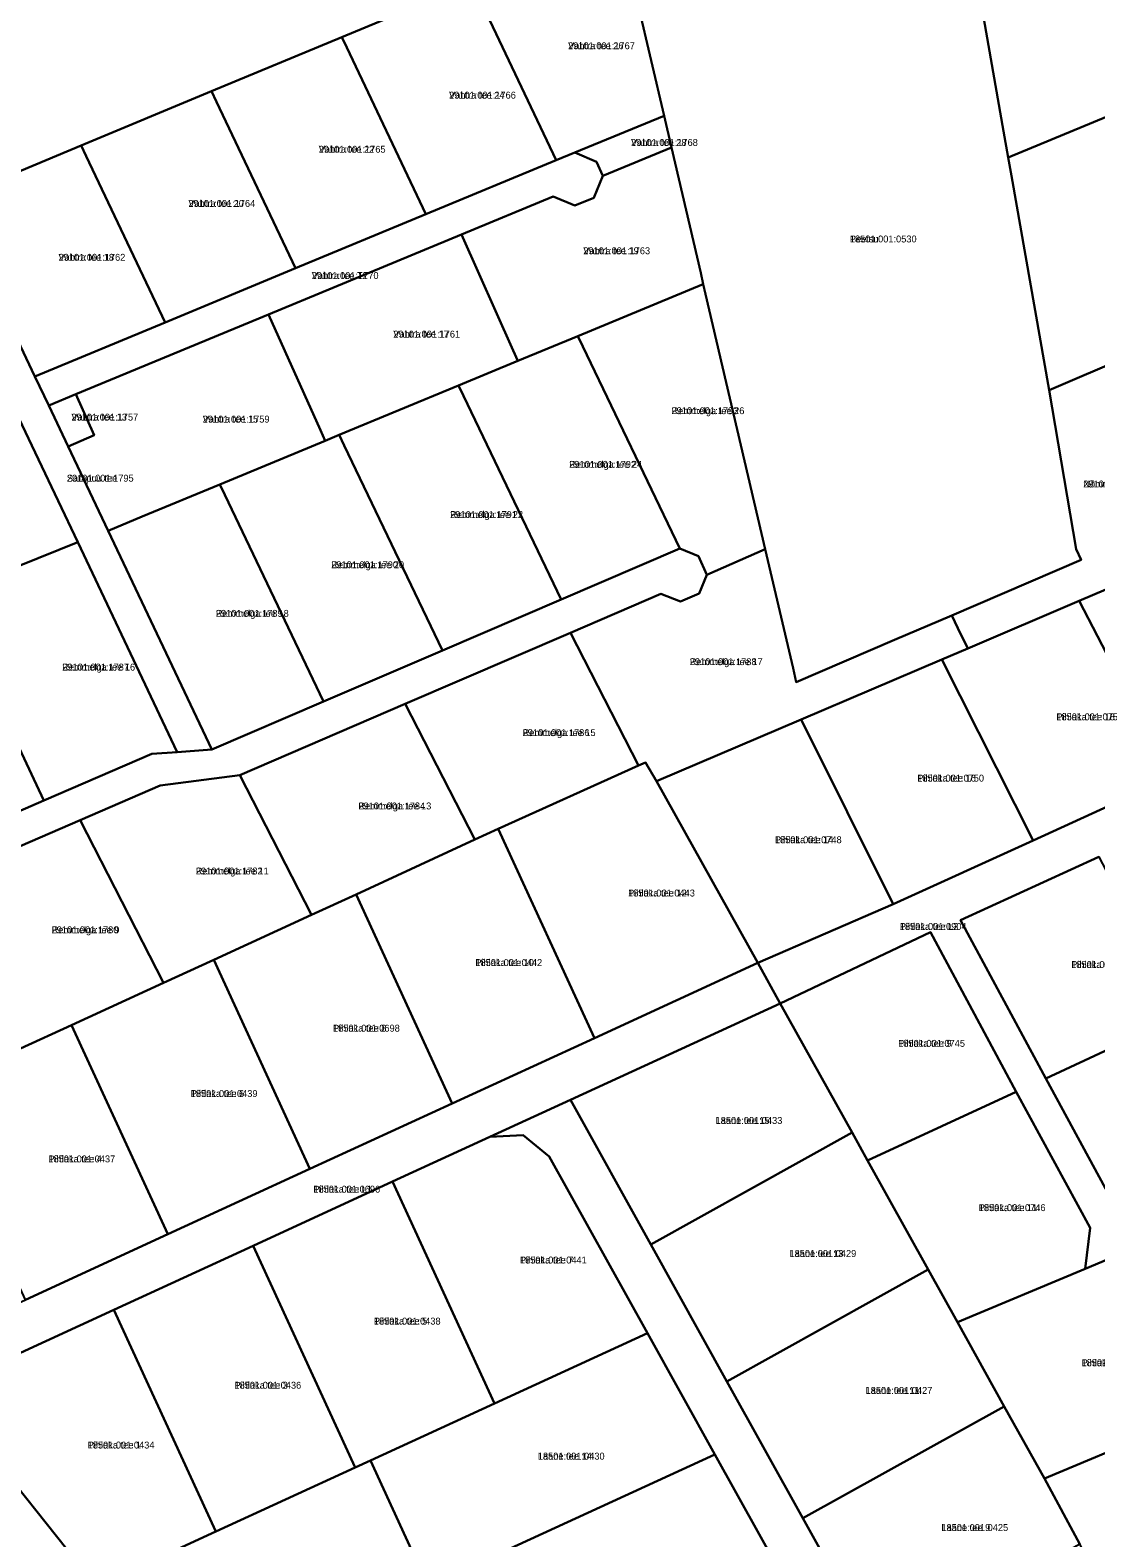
# Model space of a CAD drawing. Extents: x 660838 to 697091, y 6455678 to 6479886.
# Drawn here: x 663522.4 to 663753.8, y 6468685 to 6469012.3 of the extents above; entities that cross this region are included whole.
import ezdxf

# ---------------------------------------------------------------- set-up
doc = ezdxf.new("R2010")
doc.units = 0
for name, color, linetype in [('L_AADRESS', 7, 'Continuous'), ('PIIR', 7, 'Continuous'), ('TUNNUS', 7, 'Continuous')]:
    doc.layers.add(name, color=color, linetype=linetype)

msp = doc.modelspace()

# ---------------------------------------------------------------- linework, layer by layer
at = {"layer": 'PIIR'}
for points in [[(663713.62, 6469105.91), (663746.93, 6469119.34), (663749.47, 6469109.68), (663756.71, 6469091.04), (663760.88, 6469081.29), (663769.48, 6469063.27), (663778.44, 6469046.32), (663796.85, 6469010.36), (663794.27, 6469009.28), (663762.57, 6468996.15), (663734.77, 6468984.63), (663733.79, 6468990.38), (663721.13, 6469062.36), (663720.66, 6469065.11), (663720.33, 6469067.06)], [(663486.87, 6469014.31), (663713.62, 6469105.91), (663720.33, 6469067.06), (663720.66, 6469065.11), (663650.19, 6469035.8), (663618.39, 6469022.56), (663590.11, 6469010.8), (663561.82, 6468999.03), (663533.52, 6468987.26), (663507.5, 6468976.43), (663507.24, 6468975.83), (663505.45, 6468975.08)], [(663720.66, 6469065.11), (663721.13, 6469062.36), (663733.79, 6468990.38), (663734.77, 6468984.63), (663735.47, 6468980.66), (663743.64, 6468934.13), (663749.54, 6468899.66), (663750.6, 6468897.35), (663722.52, 6468885.28), (663710.12, 6468879.95), (663688.77, 6468870.78), (663688.07, 6468873.8), (663682.01, 6468899.68), (663669.09, 6468955.03), (663668.58, 6468957.2), (663668.01, 6468959.61), (663661.64, 6468986.83), (663660.05, 6468993.7), (663651.59, 6469029.84), (663650.19, 6469035.8)], [(663618.39, 6469022.56), (663650.19, 6469035.8), (663651.59, 6469029.84), (663660.05, 6468993.7), (663640.72, 6468985.74), (663636.66, 6468984.06), (663619.46, 6469020.3)], [(663590.11, 6469010.8), (663618.39, 6469022.56), (663619.46, 6469020.3), (663636.66, 6468984.06), (663608.35, 6468972.33), (663591.18, 6469008.54)], [(663561.82, 6468999.03), (663590.11, 6469010.8), (663591.18, 6469008.54), (663608.35, 6468972.33), (663580.05, 6468960.61), (663562.89, 6468996.77)], [(663533.52, 6468987.26), (663561.82, 6468999.03), (663562.89, 6468996.77), (663580.05, 6468960.61), (663551.73, 6468948.87), (663534.59, 6468984.99)], [(663734.77, 6468984.63), (663762.57, 6468996.15), (663764.4, 6468992.6), (663785.23, 6468951.96), (663760.77, 6468941.45), (663743.64, 6468934.13), (663735.47, 6468980.66)], [(663640.72, 6468985.74), (663660.05, 6468993.7), (663661.64, 6468986.83), (663646.75, 6468980.66), (663645.42, 6468983.74)], [(663507.5, 6468976.43), (663533.52, 6468987.26), (663534.59, 6468984.99), (663551.73, 6468948.87), (663523.45, 6468937.16), (663505.45, 6468975.08), (663507.24, 6468975.83)], [(663636.66, 6468984.06), (663640.72, 6468985.74), (663645.42, 6468983.74), (663646.75, 6468980.66), (663644.79, 6468975.93), (663640.72, 6468974.24), (663635.99, 6468976.21), (663616.08, 6468967.96), (663574.21, 6468950.61), (663532.35, 6468933.27), (663526.45, 6468930.82), (663523.45, 6468937.16), (663551.73, 6468948.87), (663580.05, 6468960.61), (663608.35, 6468972.33)], [(663646.75, 6468980.66), (663661.64, 6468986.83), (663668.01, 6468959.61), (663668.58, 6468957.2), (663641.33, 6468945.9), (663628.34, 6468940.52), (663627.32, 6468942.8), (663616.08, 6468967.96), (663635.99, 6468976.21), (663640.72, 6468974.24), (663644.79, 6468975.93)], [(663498.96, 6468972.37), (663505.45, 6468975.08), (663523.45, 6468937.16), (663526.45, 6468930.82), (663530.66, 6468921.94), (663539.34, 6468903.64), (663561.84, 6468856.19), (663554.36, 6468855.61), (663532.75, 6468901.15), (663519.97, 6468928.09), (663516.97, 6468934.43)], [(663574.21, 6468950.61), (663616.08, 6468967.96), (663627.32, 6468942.8), (663628.34, 6468940.52), (663615.44, 6468935.17), (663589.51, 6468924.43), (663586.48, 6468923.17), (663585.46, 6468925.45)], [(663641.33, 6468945.9), (663668.58, 6468957.2), (663669.09, 6468955.03), (663682.01, 6468899.68), (663669.31, 6468894.09), (663667.57, 6468898.13), (663663.49, 6468899.77), (663642.41, 6468943.65)], [(663532.35, 6468933.27), (663574.21, 6468950.61), (663585.46, 6468925.45), (663586.48, 6468923.17), (663563.61, 6468913.7), (663546.73, 6468906.7), (663539.34, 6468903.64), (663530.66, 6468921.94), (663536.32, 6468924.39)], [(663628.34, 6468940.52), (663641.33, 6468945.9), (663642.41, 6468943.65), (663663.49, 6468899.77), (663637.7, 6468888.71), (663616.52, 6468932.92), (663615.44, 6468935.17)], [(663743.64, 6468934.13), (663760.77, 6468941.45), (663759.06, 6468937.44), (663760.77, 6468933.32), (663763.65, 6468932.16), (663779.64, 6468900.95), (663750.22, 6468888.4), (663725.98, 6468878.05), (663723.87, 6468882.46), (663722.52, 6468885.28), (663750.6, 6468897.35), (663749.54, 6468899.66)], [(663526.45, 6468930.82), (663532.35, 6468933.27), (663536.32, 6468924.39), (663530.66, 6468921.94)], [(663589.51, 6468924.43), (663615.44, 6468935.17), (663616.52, 6468932.92), (663637.7, 6468888.71), (663611.97, 6468877.68), (663590.6, 6468922.17)], [(663479.86, 6468911.75), (663519.97, 6468928.09), (663532.75, 6468901.15), (663520.04, 6468896.06), (663518.06, 6468895.26), (663504.39, 6468889.72), (663492.61, 6468884.94), (663491.54, 6468887.21)], [(663586.48, 6468923.17), (663589.51, 6468924.43), (663590.6, 6468922.17), (663611.97, 6468877.68), (663586.13, 6468866.6), (663564.69, 6468911.44), (663563.61, 6468913.7)], [(663546.73, 6468906.7), (663563.61, 6468913.7), (663564.69, 6468911.44), (663586.13, 6468866.6), (663561.84, 6468856.19), (663539.34, 6468903.64)], [(663520.04, 6468896.06), (663532.75, 6468901.15), (663554.36, 6468855.61), (663548.83, 6468855.19), (663525.39, 6468845.05), (663505.46, 6468887.45), (663504.39, 6468889.72), (663518.06, 6468895.26)], [(663669.31, 6468894.09), (663682.01, 6468899.68), (663688.07, 6468873.8), (663688.77, 6468870.78), (663710.12, 6468879.95), (663722.52, 6468885.28), (663723.87, 6468882.46), (663725.98, 6468878.05), (663720.37, 6468875.68), (663689.86, 6468862.67), (663658.45, 6468849.26), (663656.03, 6468853.33), (663654.54, 6468852.67), (663639.77, 6468881.51), (663659.37, 6468889.97), (663663.63, 6468888.27), (663667.67, 6468890)], [(663750.22, 6468888.4), (663779.64, 6468900.95), (663779.88, 6468901.05), (663799.48, 6468863.6), (663770.09, 6468850.07)], [(663492.61, 6468884.94), (663504.39, 6468889.72), (663505.46, 6468887.45), (663525.39, 6468845.05), (663498.76, 6468833.53), (663478.54, 6468876.54), (663477.48, 6468878.81)], [(663720.37, 6468875.68), (663725.98, 6468878.05), (663750.22, 6468888.4), (663770.09, 6468850.07), (663740.2, 6468836.43)], [(663603.87, 6468866.04), (663639.77, 6468881.51), (663654.54, 6468852.67), (663624.06, 6468838.96), (663618.96, 6468836.62)], [(663689.86, 6468862.67), (663720.37, 6468875.68), (663740.2, 6468836.43), (663709.8, 6468822.59)], [(663567.98, 6468850.56), (663603.87, 6468866.04), (663618.96, 6468836.62), (663593.2, 6468824.71), (663583.48, 6468820.25)], [(663658.45, 6468849.26), (663689.86, 6468862.67), (663709.8, 6468822.59), (663680.43, 6468809.82)], [(663550.63, 6468848.34), (663567.98, 6468850.56), (663583.48, 6468820.25), (663562.29, 6468810.5), (663551.4, 6468805.53), (663533.31, 6468840.85)], [(663680.43, 6468809.82), (663644.97, 6468793.52), (663624.06, 6468838.96), (663654.54, 6468852.67), (663656.03, 6468853.33), (663658.45, 6468849.26)], [(663502.79, 6468827.65), (663533.31, 6468840.85), (663551.4, 6468805.53), (663531.41, 6468796.35), (663520.34, 6468791.26)], [(663644.97, 6468793.52), (663614.08, 6468779.32), (663593.2, 6468824.71), (663618.96, 6468836.62), (663624.06, 6468838.96)], [(663724.42, 6468819.11), (663754.42, 6468832.89), (663772.49, 6468798.52), (663742.98, 6468784.76)], [(663583.18, 6468765.12), (663562.29, 6468810.5), (663583.48, 6468820.25), (663593.2, 6468824.71), (663614.08, 6468779.32)], [(663685.3, 6468801.05), (663717.91, 6468816.54), (663736.48, 6468781.86), (663704.21, 6468766.94), (663700.88, 6468773)], [(663496.35, 6468725.18), (663521.4, 6468736.72), (663552.29, 6468750.92), (663583.18, 6468765.12), (663614.08, 6468779.32), (663644.97, 6468793.52), (663680.43, 6468809.82), (663685.3, 6468801.05), (663639.74, 6468780.11), (663622.2, 6468772.05), (663601.1, 6468762.35), (663570.84, 6468748.44), (663540.58, 6468734.53), (663510.99, 6468720.93), (663507.1, 6468716.16), (663508.46, 6468710.09)], [(663583.18, 6468765.12), (663552.29, 6468750.92), (663531.41, 6468796.35), (663551.4, 6468805.53), (663562.29, 6468810.5)], [(663639.74, 6468780.11), (663685.3, 6468801.05), (663700.88, 6468773), (663657.18, 6468748.72)], [(663742.98, 6468784.76), (663772.49, 6468798.52), (663792.65, 6468760.54), (663766.6, 6468749.73), (663759.16, 6468754.82)], [(663552.29, 6468750.92), (663521.4, 6468736.72), (663500.5, 6468782.17), (663520.34, 6468791.26), (663531.41, 6468796.35)], [(663704.21, 6468766.94), (663736.48, 6468781.86), (663752.55, 6468752.34), (663751.52, 6468743.45), (663723.79, 6468731.86), (663717.4, 6468743.28)], [(663656.44, 6468729.45), (663623.23, 6468714.19), (663601.1, 6468762.35), (663622.2, 6468772.05), (663629.49, 6468772.47), (663635.12, 6468767.82)], [(663657.18, 6468748.72), (663700.88, 6468773), (663704.21, 6468766.94), (663717.4, 6468743.28), (663673.69, 6468719)], [(663601.1, 6468762.35), (663623.23, 6468714.19), (663596.34, 6468701.83), (663592.98, 6468700.28), (663570.84, 6468748.44)], [(663570.84, 6468748.44), (663592.98, 6468700.28), (663562.72, 6468686.37), (663540.58, 6468734.53)], [(663742.64, 6468697.91), (663733.91, 6468713.56), (663723.79, 6468731.86), (663751.52, 6468743.45), (663759.25, 6468746.68), (663776.61, 6468714.25), (663777.9, 6468711.83), (663777.75, 6468711.77), (663766.9, 6468707.5), (663766.15, 6468707.76)], [(663673.69, 6468719), (663717.4, 6468743.28), (663723.79, 6468731.86), (663733.91, 6468713.56), (663690.2, 6468689.27)], [(663540.58, 6468734.53), (663562.72, 6468686.37), (663536.85, 6468674.48), (663508.46, 6468710.09), (663507.1, 6468716.16), (663510.99, 6468720.93)], [(663596.34, 6468701.83), (663623.23, 6468714.19), (663656.44, 6468729.45), (663671.05, 6468703.15), (663608.87, 6468674.57)], [(663742.64, 6468697.91), (663766.15, 6468707.76), (663766.9, 6468707.5), (663777.75, 6468711.77), (663777.9, 6468711.83), (663798.31, 6468719.47), (663799.8, 6468716.38), (663828.99, 6468657.82), (663820.81, 6468654.22), (663815.27, 6468665.42), (663770.39, 6468646.95), (663767.34, 6468652.41), (663750.34, 6468683.68)], [(663690.2, 6468689.27), (663733.91, 6468713.56), (663742.64, 6468697.91), (663750.34, 6468683.68), (663706.77, 6468659.47)], [(663685.67, 6468676.85), (663621.4, 6468647.31), (663608.87, 6468674.57), (663671.05, 6468703.15)], [(663536.85, 6468674.48), (663562.72, 6468686.37), (663592.98, 6468700.28), (663596.34, 6468701.83), (663608.87, 6468674.57), (663550.97, 6468647.98), (663545.12, 6468661.66)]]:
    msp.add_lwpolyline(points, close=True, dxfattribs=at)
for points in [[(663498.76, 6468833.53), (663525.39, 6468845.05), (663548.83, 6468855.19), (663554.36, 6468855.61), (663561.84, 6468856.19), (663586.13, 6468866.6), (663611.97, 6468877.68), (663637.7, 6468888.71), (663663.49, 6468899.77), (663667.57, 6468898.13), (663669.31, 6468894.09), (663667.67, 6468890), (663663.63, 6468888.27), (663659.37, 6468889.97), (663639.77, 6468881.51), (663603.87, 6468866.04), (663567.98, 6468850.56), (663550.63, 6468848.34), (663533.31, 6468840.85), (663502.79, 6468827.65)], [(663759.25, 6468746.68), (663751.52, 6468743.45), (663752.55, 6468752.34), (663736.48, 6468781.86), (663717.91, 6468816.54), (663685.3, 6468801.05), (663680.43, 6468809.82), (663709.8, 6468822.59), (663740.2, 6468836.43), (663770.09, 6468850.07)], [(663754.42, 6468832.89), (663724.42, 6468819.11), (663742.98, 6468784.76), (663759.16, 6468754.82)], [(663685.67, 6468676.85), (663671.05, 6468703.15), (663656.44, 6468729.45), (663635.12, 6468767.82), (663629.49, 6468772.47), (663622.2, 6468772.05), (663639.74, 6468780.11), (663657.18, 6468748.72), (663673.69, 6468719), (663690.2, 6468689.27), (663706.77, 6468659.47)], [(663513.22, 6468678.87), (663487.82, 6468710.24), (663496.35, 6468725.18), (663508.46, 6468710.09), (663536.85, 6468674.48)]]:
    msp.add_lwpolyline(points, dxfattribs=at)

# ---------------------------------------------------------------- texts
at = {"layer": 'L_AADRESS'}
for s, p in [('Vahtra tee 26', (663639.22, 6469008.18)), ('Vahtra tee 24', (663613.38, 6468997.45)), ('Vahtra tee 28', (663652.89, 6468987.18)), ('Vahtra tee 22', (663585.09, 6468985.7)), ('Vahtra tee 20', (663556.79, 6468973.95)), ('Vahtra tee 19', (663642.53, 6468963.67)), ('Peetsu', (663700.39, 6468966.23)), ('Vahtra tee 18', (663528.59, 6468962.25)), ('Vahtra tee T2', (663583.57, 6468958.28)), ('Vahtra tee 17', (663601.28, 6468945.57)), ('Vahtra tee 13', (663531.39, 6468927.56)), ('Remmelga tee 26', (663661.67, 6468928.95)), ('Vahtra tee 15', (663559.9, 6468927.12)), ('Remmelga tee 24', (663639.46, 6468917.3)), ('Sarapuu tee', (663530.4, 6468914.3)), ('Nõmmevälja tee 1', (663751.08, 6468913.04)), ('Remmelga tee 22', (663613.61, 6468906.4)), ('Remmelga tee 20', (663587.79, 6468895.51)), ('Remmelga tee 18', (663562.74, 6468884.96)), ('Remmelga tee 16', (663529.38, 6468873.29)), ('Remmelga tee 17', (663665.64, 6468874.47)), ('Pihlaka tee 18', (663745.23, 6468862.5)), ('Remmelga tee 15', (663629.36, 6468859.07)), ('Pihlaka tee 16', (663715.03, 6468849.19)), ('Remmelga tee 13', (663593.69, 6468843.15)), ('Pihlaka tee 14', (663684.12, 6468835.82)), ('Remmelga tee 11', (663558.39, 6468829.03)), ('Pihlaka tee 12', (663652.25, 6468824.25)), ('Remmelga tee 9', (663527.09, 6468816.26)), ('Pihlaka tee L2', (663711.24, 6468816.99)), ('Pihlaka tee 10', (663619.09, 6468809.15)), ('Pihlaka tee 19', (663748.46, 6468808.73)), ('Pihlaka tee 8', (663588.18, 6468794.91)), ('Pihlaka tee 9', (663710.89, 6468791.62)), ('Pihlaka tee 6', (663557.29, 6468780.72)), ('Laane tee 15', (663671.24, 6468774.88)), ('Pihlaka tee 4', (663526.39, 6468766.53)), ('Pihlaka tee L1', (663583.92, 6468759.96)), ('Pihlaka tee 11', (663728.38, 6468755.95)), ('Pihlaka tee 7', (663628.77, 6468744.58)), ('Laane tee 13', (663687.29, 6468746)), ('Pihlaka tee 5', (663597.04, 6468731.32)), ('Pihlaka tee 13', (663750.69, 6468722.29)), ('Pihlaka tee 3', (663566.78, 6468717.4)), ('Laane tee 11', (663703.81, 6468716.28)), ('Pihlaka tee 1', (663534.91, 6468704.42)), ('Laane tee 14', (663632.65, 6468702.01)), ('Laane tee 9', (663720.27, 6468686.51))]:
    msp.add_text(s, height=1.5, dxfattribs=at).set_placement(p)
at = {"layer": 'TUNNUS'}
for s, p in [('29101:001:1767', (663639.22, 6469008.18)), ('29101:001:1766', (663613.38, 6468997.45)), ('29101:001:1768', (663652.89, 6468987.18)), ('29101:001:1765', (663585.09, 6468985.7)), ('29101:001:1764', (663556.79, 6468973.95)), ('29101:001:1763', (663642.53, 6468963.67)), ('18501:001:0530', (663700.39, 6468966.23)), ('29101:001:1762', (663528.59, 6468962.25)), ('29101:001:1770', (663583.57, 6468958.28)), ('29101:001:1761', (663601.28, 6468945.57)), ('29101:001:1757', (663531.39, 6468927.56)), ('29101:001:1793', (663661.67, 6468928.95)), ('29101:001:1759', (663559.9, 6468927.12)), ('29101:001:1792', (663639.46, 6468917.3)), ('29101:001:1795', (663530.4, 6468914.3)), ('29101:001:0498', (663751.08, 6468913.04)), ('29101:001:1791', (663613.61, 6468906.4)), ('29101:001:1790', (663587.79, 6468895.51)), ('29101:001:1789', (663562.74, 6468884.96)), ('29101:001:1787', (663529.38, 6468873.29)), ('29101:001:1788', (663665.64, 6468874.47)), ('18501:001:0752', (663745.23, 6468862.5)), ('29101:001:1786', (663629.36, 6468859.07)), ('18501:001:0750', (663715.03, 6468849.19)), ('29101:001:1784', (663593.69, 6468843.15)), ('18501:001:0748', (663684.12, 6468835.82)), ('29101:001:1782', (663558.39, 6468829.03)), ('18501:001:0443', (663652.25, 6468824.25)), ('29101:001:1780', (663527.09, 6468816.26)), ('18501:001:0904', (663711.24, 6468816.99)), ('18501:001:0442', (663619.09, 6468809.15)), ('18501:001:0753', (663748.46, 6468808.73)), ('18501:001:0698', (663588.18, 6468794.91)), ('18501:001:0745', (663710.89, 6468791.62)), ('18501:001:0439', (663557.29, 6468780.72)), ('18501:001:0433', (663671.24, 6468774.88)), ('18501:001:0437', (663526.39, 6468766.53)), ('18501:001:0696', (663583.92, 6468759.96)), ('18501:001:0746', (663728.38, 6468755.95)), ('18501:001:0441', (663628.77, 6468744.58)), ('18501:001:0429', (663687.29, 6468746)), ('18501:001:0438', (663597.04, 6468731.32)), ('18501:001:0747', (663750.69, 6468722.29)), ('18501:001:0436', (663566.78, 6468717.4)), ('18501:001:0427', (663703.81, 6468716.28)), ('18501:001:0434', (663534.91, 6468704.42)), ('18501:001:0430', (663632.65, 6468702.01)), ('18501:001:0425', (663720.27, 6468686.51))]:
    msp.add_text(s, height=1.5, dxfattribs=at).set_placement(p)

doc.saveas('drawing.dxf')
